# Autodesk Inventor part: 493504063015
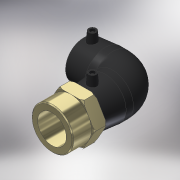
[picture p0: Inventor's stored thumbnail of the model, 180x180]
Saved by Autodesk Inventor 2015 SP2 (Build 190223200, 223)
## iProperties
Created: 2017-06
Part Number: 493504063015
Material: Generic
Description: PLASSON 90° ELBOW FEMALE TRANSITION 63-1.1/2''
Document SubType Name: Modeling
Designer: KIM
Mass: 552.196 g
Surface Area: 991.574 cm^2
Volume: 552.196 cm^3
Density: 1 g/cm^3
Appearance: Rubber - Black
Author: KIM
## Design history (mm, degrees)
derived "493504.ipt"
feature "Solid1::493504.ipt"
tag "TaggingFeature1"
body "Solid1"
other parameters: "d2" = 82, "d4" = 43.66667, "d5" = 73.8, "d8" = 168 deg, "d10" = 22.8, "d11" = 7.6, "d29" = 59, "d30" = 15, "d31" = 72.05, "d34" = 5 deg, "d41" = 4, "d42" = 14, "d43" = 0, "d49" = 63, "d50" = 53.55, "d51" = 22.8, "d52" = 57, "d54" = 90 deg, "d57" = 63, "d58" = 57, "d59" = 0, "d61" = 90 deg, "d86" = 3, "d87" = 0, "d93" = 0.1, "d96" = 44.845, "d97" = 48, "d99" = 82, "d100" = 24, "d107" = 12, "d108" = 0, "d109" = 1.89, "d112" = 45 deg, "d113" = 45 deg, "d114" = 3.15, "d_" = 63, "L_" = 161, "L_1" = 57, "D_" = 48, "A_" = 59, "d_2" = 12, "D_1" = 82, "Rp_" = 44.845
